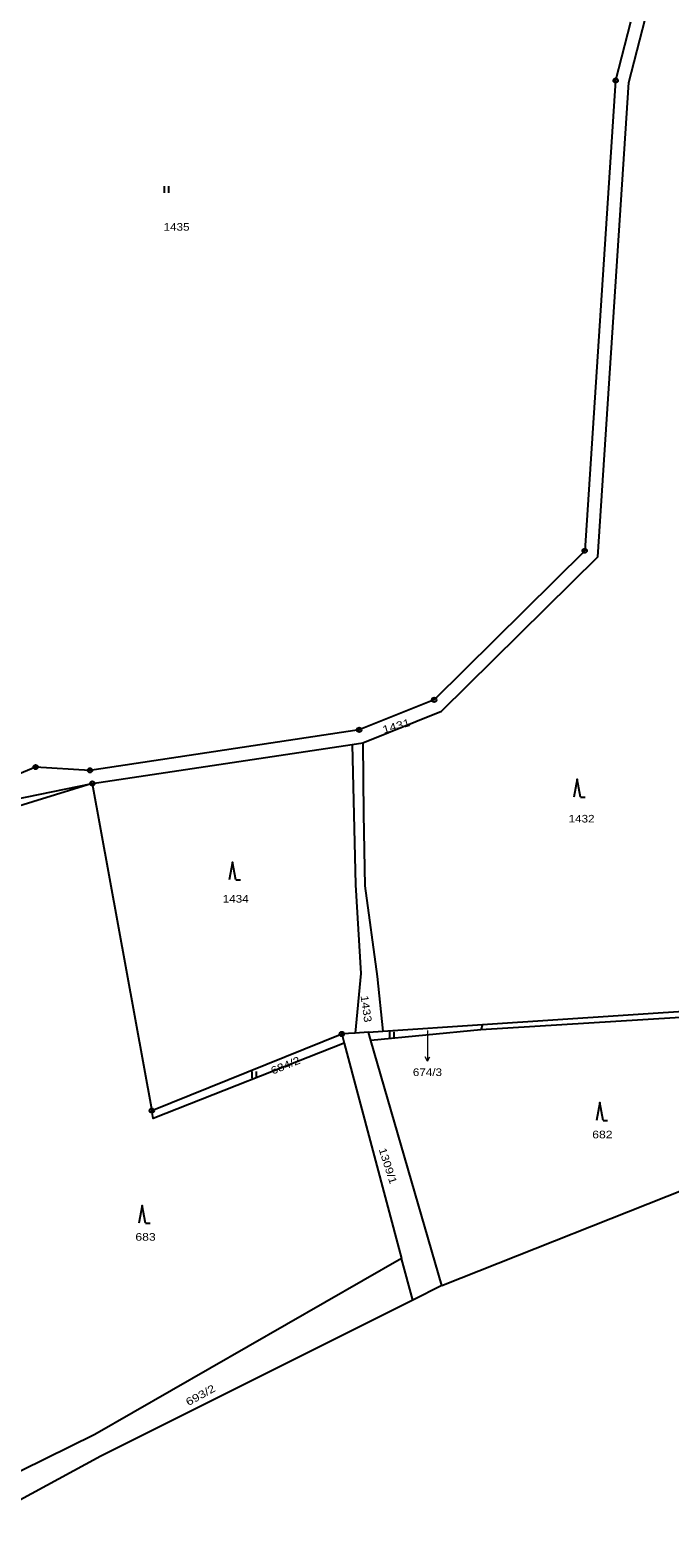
# Model space of a CAD drawing. Extents: x -872229 to -869198, y -1075981 to -1074329.
# Drawn here: x -870632.3 to -870489.1, y -1075924.5 to -1075586.7 of the extents above; entities that cross this region are included whole.
import ezdxf
from ezdxf.enums import TextEntityAlignment as Align

# ---------------------------------------------------------------- set-up
doc = ezdxf.new("R2010")
doc.units = 0
doc.header["$LTSCALE"] = 0.68
for name, color, linetype, lineweight in [('1', 7, 'Continuous', 25), ('3', 7, 'Continuous', 25), ('7', 7, 'Continuous', 13), ('8', 7, 'Continuous', 25)]:
    doc.layers.add(name, color=color, linetype=linetype, lineweight=lineweight)
doc.layers.add('2', color=7, linetype='Continuous')

msp = doc.modelspace()

# ---------------------------------------------------------------- linework, layer by layer
at = {"layer": '1'}
for p, q in [((-870618.4, -1075755.49), (-870650.51, -1075765.39)), ((-870618.4, -1075755.49), (-870605.06, -1075828.76)), ((-870605.06, -1075828.76), (-870562.55, -1075811.59)), ((-870556.56, -1075811.18), (-870553.35, -1075810.97)), ((-870531.01, -1075809.47), (-870531.41, -1075810.63)), ((-870540.14, -1075867.94), (-870556.01, -1075813.08)), ((-870540.14, -1075867.94), (-870448.9, -1075831.7)), ((-870546.66, -1075871.21), (-870549.14, -1075861.93)), ((-870540.14, -1075867.94), (-870546.66, -1075871.21))]:
    msp.add_line(p, q, dxfattribs=at)
for points in [[(-870557.85, -1075746.37), (-870540.19, -1075739.3), (-870505.25, -1075704.66), (-870498.26, -1075598.45), (-870480.43, -1075529.12)], [(-870497.88, -1075584.92), (-870501.24, -1075597.99), (-870508.17, -1075703.33), (-870541.87, -1075736.74), (-870558.64, -1075743.46), (-870618.91, -1075752.53), (-870631.08, -1075751.8), (-870646.39, -1075758.16), (-870662.6, -1075767.96)], [(-870531.01, -1075809.47), (-870465.83, -1075805.11), (-870466.06, -1075737.62), (-870469.57, -1075719.09)], [(-870650.51, -1075765.39), (-870645.07, -1075760.95), (-870618.4, -1075755.49), (-870560.25, -1075746.77), (-870557.85, -1075746.37)], [(-870560.25, -1075746.77), (-870559.51, -1075778.18), (-870558.26, -1075798.03), (-870559.56, -1075811.39)], [(-870557.85, -1075746.37), (-870557.65, -1075762.37), (-870557.39, -1075778.39), (-870554.62, -1075798.71), (-870553.35, -1075810.97), (-870531.01, -1075809.47)], [(-870457.7, -1075806.11), (-870531.41, -1075810.63), (-870556.01, -1075813.08)], [(-870556.01, -1075813.08), (-870556.56, -1075811.18), (-870559.56, -1075811.39), (-870562.55, -1075811.59), (-870562, -1075813.65), (-870549.14, -1075861.93)], [(-870562, -1075813.65), (-870604.75, -1075830.51), (-870605.06, -1075828.76)], [(-870549.14, -1075861.93), (-870617.86, -1075901.31), (-870650.72, -1075917.52)], [(-870546.66, -1075871.21), (-870616.52, -1075906.2), (-870650.23, -1075924.48)]]:
    msp.add_lwpolyline(points, dxfattribs=at)
at = {"layer": '3'}
for p, q in [((-870602.251, -1075623.14), (-870602.251, -1075621.64)), ((-870601.25, -1075623.14), (-870601.25, -1075621.64)), ((-870509.08, -1075758.53), (-870508.084, -1075758.53)), ((-870586.25, -1075777.09), (-870585.254, -1075777.09)), ((-870551.821, -1075812.59), (-870551.821, -1075811.09)), ((-870550.82, -1075812.59), (-870550.82, -1075811.09)), ((-870582.621, -1075821.53), (-870582.621, -1075820.03)), ((-870581.62, -1075821.53), (-870581.62, -1075820.03)), ((-870504.06, -1075830.98), (-870503.064, -1075830.98)), ((-870606.45, -1075853.99), (-870605.454, -1075853.99))]:
    msp.add_line(p, q, dxfattribs=at)
for points in [[(-870509.08, -1075758.53), (-870509.83, -1075754.53), (-870510.58, -1075758.53)], [(-870586.25, -1075777.09), (-870587, -1075773.09), (-870587.75, -1075777.09)], [(-870504.06, -1075830.98), (-870504.81, -1075826.98), (-870505.56, -1075830.98)], [(-870606.45, -1075853.99), (-870607.2, -1075849.99), (-870607.95, -1075853.99)]]:
    msp.add_lwpolyline(points, dxfattribs=at)
at = {"layer": '7'}
msp.add_line((-870543.37, -1075817.711), (-870542.869, -1075816.71), dxfattribs=at)
msp.add_lwpolyline([(-870543.37, -1075810.85), (-870543.37, -1075814.71), (-870543.37, -1075817.711), (-870543.871, -1075816.71)], dxfattribs=at)
at = {"layer": '8'}
for centre, radius in [((-870501.24, -1075597.9899), 0.5), ((-870501.24, -1075597.9899), 0.0303), ((-870508.17, -1075703.3299), 0.5), ((-870508.17, -1075703.3299), 0.0303), ((-870541.87, -1075736.7399), 0.5), ((-870541.87, -1075736.7399), 0.0303), ((-870558.64, -1075743.4599), 0.5), ((-870558.64, -1075743.4599), 0.0303), ((-870631.08, -1075751.7999), 0.5), ((-870631.08, -1075751.7999), 0.0303), ((-870618.91, -1075752.5299), 0.5), ((-870618.91, -1075752.5299), 0.0303), ((-870618.4, -1075755.4899), 0.5), ((-870618.4, -1075755.4899), 0.0303), ((-870562.55, -1075811.5899), 0.5), ((-870562.55, -1075811.5899), 0.0303), ((-870605.06, -1075828.7599), 0.5), ((-870605.06, -1075828.7599), 0.0303)]:
    msp.add_circle(centre, radius, dxfattribs=at)

# ---------------------------------------------------------------- texts
at = {"layer": '2'}
for s, width, p in [('1435', 1.15, (-870602.44, -1075631.63)), ('1432', 1.15, (-870511.77, -1075764.21)), ('1434', 1.15, (-870589.2, -1075782.16)), ('682', 1.2, (-870506.48, -1075834.97)), ('683', 1.2, (-870608.75, -1075857.91))]:
    msp.add_text(s, height=1.7, dxfattribs=dict(at, width=width)).set_placement(p)
for s, rotation, width, p in [('1431', 16, 1.25, (-870553.155, -1075744.297)), ('1433', 278, 1.2, (-870558.331, -1075803.068)), ('684/2', 22, 1.2, (-870578.001, -1075820.708)), ('1309/1', 288, 1.2, (-870554.308, -1075837.432)), ('693/2', 29, 1.25, (-870596.877, -1075894.973))]:
    msp.add_text(s, height=1.7, rotation=rotation, dxfattribs=dict(at, width=width)).set_placement(p)
at = {"layer": '2', "width": 1.15}
msp.add_text('674/3', height=1.7, dxfattribs=at).set_placement((-870543.369, -1075821.01), align=Align.CENTER)

doc.saveas('drawing.dxf')
